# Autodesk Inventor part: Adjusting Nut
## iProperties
Shininess: 41.0
Length Units: 11272
Angle Units: 11279
Time Units: 11290
Mass Units: 11286
Length Display Precision: 4
Angle Display Precision: 2
Compacted: True
Company: Autodesk
Manager: Lebovitz
Created: 2000-11
Part Number: Adjusting Nut
Document SubType Name: Modeling
Designer: The PD Team
Project: Inventor Samples
Checked By: The PD Team
Density: 0.0
Volumn: 0.0
Area: 0.0
PropertySet Name: Model Information
Control State: 0
Master: False
Checked Out: False
Author: The PD Team
Revision Number: A
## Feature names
1. Revolution1
2. Extrusion1
3. Revolution2
4. Extrusion2
5. Fillet1
